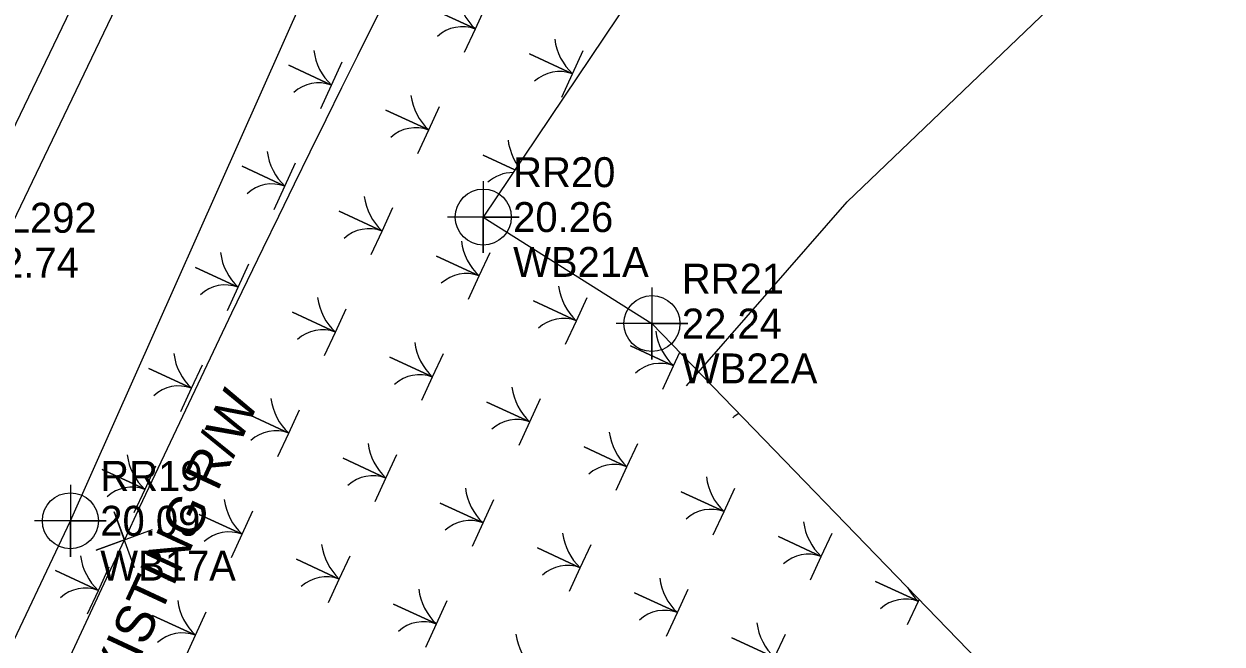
# Model space of a CAD drawing. Extents: x 2532037 to 2533565, y 713396 to 716867.
# Drawn here: x 2532941.6 to 2533041.8, y 715729.7 to 715781.5 of the extents above; entities that cross this region are included whole.
import ezdxf

# ---------------------------------------------------------------- set-up
doc = ezdxf.new("R2010")
doc.units = 0
for name, color, linetype in [('Exist Environmental Wetland Boundary', 7, 'Continuous'), ('Exist Environmental Wetland Boundary Cogo Comment', 7, 'Continuous'), ('Exist Environmental Wetland Boundary Cogo Elevation', 7, 'Continuous'), ('Exist Environmental Wetland Boundary Cogo Number', 7, 'Continuous'), ('Exist Environmental Wetland Boundary Cogo Point CELL', 7, 'Continuous'), ('Exist Horizontal Alignment', 7, 'Continuous'), ('Exist Hydro Jurisdictional Stream or Body of Water', 7, 'Continuous'), ('Exist Right of Way Line', 7, 'Continuous'), ('Exist Right of Way Line Text', 7, 'Continuous'), ('Exist Roads Soil', 7, 'Continuous'), ('Exist Roads Soil Cogo Elevation', 7, 'Continuous'), ('Exist Roads Soil Cogo Number', 7, 'Continuous'), ('Exist Utilities Telephone UG Cable SUE LOS C', 7, 'Continuous'), ('Scratch_Level_1', 7, 'Continuous')]:
    doc.layers.add(name, color=color, linetype=linetype)

msp = doc.modelspace()

# ---------------------------------------------------------------- linework, layer by layer
at = {"layer": 'Exist Environmental Wetland Boundary'}
for p, q in [((2532945.52, 715740.02), (2532982.44, 715822.91)), ((2533006.91, 715805.38), (2532980.03, 715765.4)), ((2532980.03, 715765.4), (2532994.13, 715756.5)), ((2532994.13, 715756.5), (2533039.34, 715709.83)), ((2532911.89, 715669.14), (2532945.52, 715740.02))]:
    msp.add_line(p, q, dxfattribs=at)
at = {"layer": 'Exist Environmental Wetland Boundary Cogo Point CELL'}
for points in [[(2532980.03, 715768.4), (2532980.03, 715762.4), (2532980.03, 715765.4), (2532983.03, 715765.4), (2532977.03, 715765.4)], [(2532994.13, 715759.5), (2532994.13, 715753.5), (2532994.13, 715756.5), (2532997.13, 715756.5), (2532991.13, 715756.5)], [(2532945.52, 715743.02), (2532945.52, 715737.02), (2532945.52, 715740.02), (2532948.52, 715740.02), (2532942.52, 715740.02)]]:
    msp.add_lwpolyline(points, dxfattribs=at)
for centre in [(2532980.03, 715765.4), (2532994.13, 715756.5), (2532945.52, 715740.02)]:
    msp.add_circle(centre, 2.34, dxfattribs=at)
at = {"layer": 'Exist Horizontal Alignment'}
msp.add_arc((2534464.19, 715033.98), 1700, 148.47784, 155.05, dxfattribs=at)
at = {"layer": 'Exist Hydro Jurisdictional Stream or Body of Water'}
msp.add_lwpolyline([(2532997.01, 715751.31), (2533010.45, 715766.68), (2533032.44, 715787.74), (2533077.02, 715831.42)], dxfattribs=at)
at = {"layer": 'Exist Right of Way Line'}
msp.add_line((2532748.02, 715304.21), (2532950.04, 715738.43), dxfattribs=at)
for radius in [1730, 1670]:
    msp.add_arc((2534464.19, 715033.98), radius, 148.47784, 155.05, dxfattribs=at)
at = {"layer": 'Exist Roads Soil'}
msp.add_lwpolyline([(2532882.44, 715649.38), (2532884.45, 715653.58), (2532893.83, 715673.24), (2532904.08, 715695.07), (2532909.89, 715707.28), (2532923.66, 715737.55), (2532935.37, 715761.59), (2532947.64, 715787.12), (2532960.72, 715812.47), (2532979.3, 715846.3), (2532995.34, 715875.46), (2533008.57, 715897.69), (2533027.7, 715928.62), (2533038.6, 715945.65), (2533044.8, 715955.28)], dxfattribs=at)
at = {"layer": 'Exist Utilities Telephone UG Cable SUE LOS C'}
msp.add_lwpolyline([(2532903.55, 715664.84), (2532899.75, 715668.7), (2532897.82, 715670.96), (2532899.44, 715676.21), (2532904.79, 715688.42), (2532912.91, 715705.87), (2532926.67, 715736.12), (2532938.37, 715760.13), (2532950.62, 715785.63), (2532963.67, 715810.91), (2532982.22, 715844.69), (2532998.24, 715873.8), (2533011.42, 715895.96), (2533023.69, 715915.8)], dxfattribs=at)
at = {"layer": 'Scratch_Level_1'}
msp.add_line((2532950.04, 715738.43), (2532950.04, 715738.43), dxfattribs=at)
for points in [[(2532978.47, 715779.17), (2532979.37, 715781.12), (2532975.79, 715782.78), (2532979.37, 715781.12), (2532980.27, 715783.07)], [(2532986.59, 715775.42), (2532987.49, 715777.37), (2532983.91, 715779.03), (2532987.49, 715777.37), (2532988.39, 715779.32)], [(2532966.45, 715774.47), (2532967.35, 715776.43), (2532963.77, 715778.08), (2532967.35, 715776.43), (2532968.25, 715778.38)], [(2532974.57, 715770.72), (2532975.47, 715772.68), (2532971.89, 715774.33), (2532975.47, 715772.68), (2532976.37, 715774.63)], [(2532982.68, 715769.35), (2532980.01, 715770.58), (2532982.68, 715769.35)], [(2532962.55, 715766.03), (2532963.45, 715767.98), (2532959.87, 715769.64), (2532963.45, 715767.98), (2532964.35, 715769.93)], [(2532970.67, 715762.28), (2532971.57, 715764.23), (2532967.99, 715765.89), (2532971.57, 715764.23), (2532972.47, 715766.19)], [(2532978.79, 715758.53), (2532979.69, 715760.48), (2532976.11, 715762.14), (2532979.69, 715760.48), (2532980.6, 715762.44)], [(2532958.65, 715757.59), (2532959.55, 715759.54), (2532955.97, 715761.19), (2532959.55, 715759.54), (2532960.45, 715761.49)], [(2532986.91, 715754.78), (2532987.82, 715756.73), (2532984.23, 715758.39), (2532987.82, 715756.73), (2532988.72, 715758.69)], [(2532966.77, 715753.84), (2532967.67, 715755.79), (2532964.09, 715757.44), (2532967.67, 715755.79), (2532968.58, 715757.74)], [(2532995.04, 715751.03), (2532995.94, 715752.98), (2532992.35, 715754.64), (2532995.94, 715752.98), (2532996.45, 715754.11)], [(2532974.89, 715750.09), (2532975.8, 715752.04), (2532972.21, 715753.69), (2532975.8, 715752.04), (2532976.7, 715753.99)], [(2532954.75, 715749.14), (2532955.65, 715751.09), (2532952.07, 715752.75), (2532955.65, 715751.09), (2532956.56, 715753.05)], [(2532962.87, 715745.39), (2532963.78, 715747.34), (2532960.19, 715749), (2532963.78, 715747.34), (2532964.68, 715749.3)], [(2532983.02, 715746.34), (2532983.92, 715748.29), (2532980.33, 715749.94), (2532983.92, 715748.29), (2532984.82, 715750.24)], [(2532991.14, 715742.59), (2532992.04, 715744.54), (2532988.46, 715746.19), (2532992.04, 715744.54), (2532992.94, 715746.49)], [(2532971, 715741.64), (2532971.9, 715743.59), (2532968.32, 715745.25), (2532971.9, 715743.59), (2532972.8, 715745.55)], [(2532950.85, 715740.7), (2532951.76, 715742.65), (2532948.17, 715744.3), (2532951.76, 715742.65), (2532952.66, 715744.6)], [(2532999.26, 715738.84), (2533000.16, 715740.79), (2532996.58, 715742.44), (2533000.16, 715740.79), (2533001.06, 715742.74)], [(2532979.12, 715737.89), (2532980.02, 715739.85), (2532976.44, 715741.5), (2532980.02, 715739.85), (2532980.92, 715741.8)], [(2532950.89, 715736.08), (2532949.18, 715740.78), (2532950.04, 715738.43), (2532947.69, 715737.57), (2532952.38, 715739.29)], [(2532958.98, 715736.95), (2532959.88, 715738.9), (2532956.3, 715740.55), (2532959.88, 715738.9), (2532960.78, 715740.85)], [(2533007.38, 715735.09), (2533008.28, 715737.04), (2533004.7, 715738.7), (2533008.28, 715737.04), (2533009.18, 715738.99)], [(2532987.24, 715734.14), (2532988.14, 715736.1), (2532984.56, 715737.75), (2532988.14, 715736.1), (2532989.04, 715738.05)], [(2532967.1, 715733.2), (2532968, 715735.15), (2532964.42, 715736.8), (2532968, 715735.15), (2532968.9, 715737.1)], [(2532946.96, 715732.25), (2532947.86, 715734.2), (2532944.28, 715735.86), (2532947.86, 715734.2), (2532948.76, 715736.16)], [(2532995.36, 715730.39), (2532996.26, 715732.35), (2532992.68, 715734), (2532996.26, 715732.35), (2532997.16, 715734.3)], [(2533015.5, 715731.34), (2533016.4, 715733.29), (2533012.82, 715734.95), (2533016.4, 715733.29), (2533016.47, 715733.44)], [(2532975.22, 715729.45), (2532976.12, 715731.4), (2532972.54, 715733.05), (2532976.12, 715731.4), (2532977.02, 715733.35)], [(2532955.08, 715728.5), (2532955.98, 715730.46), (2532952.4, 715732.11), (2532955.98, 715730.46), (2532956.88, 715732.41)], [(2533003.48, 715726.64), (2533004.38, 715728.6), (2533000.8, 715730.25), (2533004.38, 715728.6), (2533005.28, 715730.55)]]:
    msp.add_lwpolyline(points, dxfattribs=at)
for centre, radius, start, end in [((2532982.66, 715784.63), 4.81, 187.3464, 226.8412), ((2532978.29, 715778.24), 3.07, 69.3593, 132.7539), ((2532970.64, 715779.93), 4.81, 187.3464, 226.8412), ((2532990.78, 715780.88), 4.81, 187.3464, 226.8412), ((2532986.41, 715774.49), 3.07, 69.3593, 132.7539), ((2532966.27, 715773.55), 3.07, 69.3593, 132.7539), ((2532978.76, 715776.18), 4.81, 187.3464, 226.8412), ((2532974.39, 715769.8), 3.07, 69.3593, 132.7539), ((2532986.88, 715772.43), 4.81, 187.3464, 214.6071), ((2532966.74, 715771.49), 4.81, 187.3464, 226.8412), ((2532982.51, 715766.05), 3.07, 89.5094, 132.7539), ((2532962.37, 715765.1), 3.07, 69.3593, 132.7539), ((2532974.86, 715767.74), 4.81, 187.3464, 226.8412), ((2532970.49, 715761.36), 3.07, 69.3593, 132.7539), ((2532982.98, 715763.99), 4.81, 187.3464, 226.8412), ((2532962.84, 715763.04), 4.81, 187.3464, 226.8412), ((2532978.61, 715757.61), 3.07, 69.3593, 132.7539), ((2532958.47, 715756.66), 3.07, 69.3593, 132.7539), ((2532991.1, 715760.24), 4.81, 187.3464, 226.8412), ((2532970.96, 715759.29), 4.81, 187.3464, 226.8412), ((2532986.73, 715753.86), 3.07, 69.3593, 132.7539), ((2532966.59, 715752.91), 3.07, 69.3593, 132.7539), ((2532999.22, 715756.49), 4.81, 187.3464, 226.8412), ((2532979.08, 715755.54), 4.81, 187.3464, 226.8412), ((2532958.94, 715754.6), 4.81, 187.3464, 226.8412), ((2532994.85, 715750.11), 3.07, 69.3593, 132.7539), ((2532954.57, 715748.22), 3.07, 69.3593, 132.7539), ((2532974.71, 715749.16), 3.07, 69.3593, 132.7539), ((2532987.2, 715751.8), 4.81, 187.3464, 226.8412), ((2532967.06, 715750.85), 4.81, 187.3464, 226.8412), ((2532982.83, 715745.41), 3.07, 69.3593, 132.7539), ((2533002.97, 715746.36), 3.07, 120.7935, 132.7539), ((2532962.69, 715744.47), 3.07, 69.3593, 132.7539), ((2532995.33, 715748.05), 4.81, 187.3464, 226.8412), ((2532975.18, 715747.1), 4.81, 187.3464, 226.8412), ((2532955.04, 715746.15), 4.81, 187.3464, 226.8412), ((2532990.95, 715741.66), 3.07, 69.3593, 132.7539), ((2532970.81, 715740.72), 3.07, 69.3593, 132.7539), ((2533003.45, 715744.3), 4.81, 187.3464, 226.8412), ((2532950.67, 715739.77), 3.07, 69.3593, 132.7539), ((2532983.31, 715743.35), 4.81, 187.3464, 226.8412), ((2532963.16, 715742.41), 4.81, 187.3464, 226.8412), ((2532999.08, 715737.91), 3.07, 69.3593, 132.7539), ((2532978.93, 715736.97), 3.07, 69.3593, 132.7539), ((2533011.57, 715740.55), 4.81, 187.3464, 226.8412), ((2532958.79, 715736.02), 3.07, 69.3593, 132.7539), ((2532991.43, 715739.6), 4.81, 187.3464, 226.8412), ((2532971.29, 715738.66), 4.81, 187.3464, 226.8412), ((2533007.2, 715734.16), 3.07, 69.3593, 132.7539), ((2532951.14, 715737.71), 4.81, 187.3464, 226.8412), ((2532987.06, 715733.22), 3.07, 69.3593, 132.7539), ((2532966.91, 715732.27), 3.07, 69.3593, 132.7539), ((2532999.55, 715735.85), 4.81, 187.3464, 226.8412), ((2532946.77, 715731.33), 3.07, 69.3593, 132.7539), ((2532979.41, 715734.91), 4.81, 187.3464, 226.8412), ((2533019.69, 715736.8), 4.81, 209.3734, 226.8412), ((2532959.27, 715733.96), 4.81, 187.3464, 226.8412), ((2533015.32, 715730.41), 3.07, 69.3593, 132.7539), ((2532995.18, 715729.47), 3.07, 69.3593, 132.7539), ((2532975.04, 715728.52), 3.07, 69.3593, 132.7539), ((2533007.67, 715732.1), 4.81, 187.3464, 226.8412), ((2532954.89, 715727.58), 3.07, 69.3593, 132.7539), ((2532987.53, 715731.16), 4.81, 187.3464, 226.8412)]:
    msp.add_arc(centre, radius, start, end, dxfattribs=at)

# ---------------------------------------------------------------- texts
at = {"layer": 'Exist Environmental Wetland Boundary Cogo Comment'}
for s, p in [('WB21A', (2532982.53, 715760.4)), ('WB22A', (2532996.63, 715751.5)), ('WB17A', (2532948.02, 715735.02))]:
    msp.add_text(s, height=2.5, dxfattribs=at).set_placement(p)
at = {"layer": 'Exist Environmental Wetland Boundary Cogo Elevation'}
for s, p in [('20.26', (2532982.53, 715764.15)), ('22.24', (2532996.63, 715755.25)), ('20.09', (2532948.02, 715738.77))]:
    msp.add_text(s, height=2.5, dxfattribs=at).set_placement(p)
at = {"layer": 'Exist Environmental Wetland Boundary Cogo Number'}
for s, p in [('RR20', (2532982.53, 715767.9)), ('RR21', (2532996.63, 715759)), ('RR19', (2532948.02, 715742.52))]:
    msp.add_text(s, height=2.5, dxfattribs=at).set_placement(p)
at = {"layer": 'Exist Right of Way Line Text'}
msp.add_text('EXISTING R/W', height=3.2, rotation=65.05, dxfattribs=at).set_placement((2532948.89, 715723.21))
at = {"layer": 'Exist Roads Soil Cogo Elevation'}
msp.add_text('22.74', height=2.5, dxfattribs=at).set_placement((2532937.87, 715760.34))
at = {"layer": 'Exist Roads Soil Cogo Number'}
msp.add_text('HL292', height=2.5, dxfattribs=at).set_placement((2532937.87, 715764.09))

doc.saveas('drawing.dxf')
